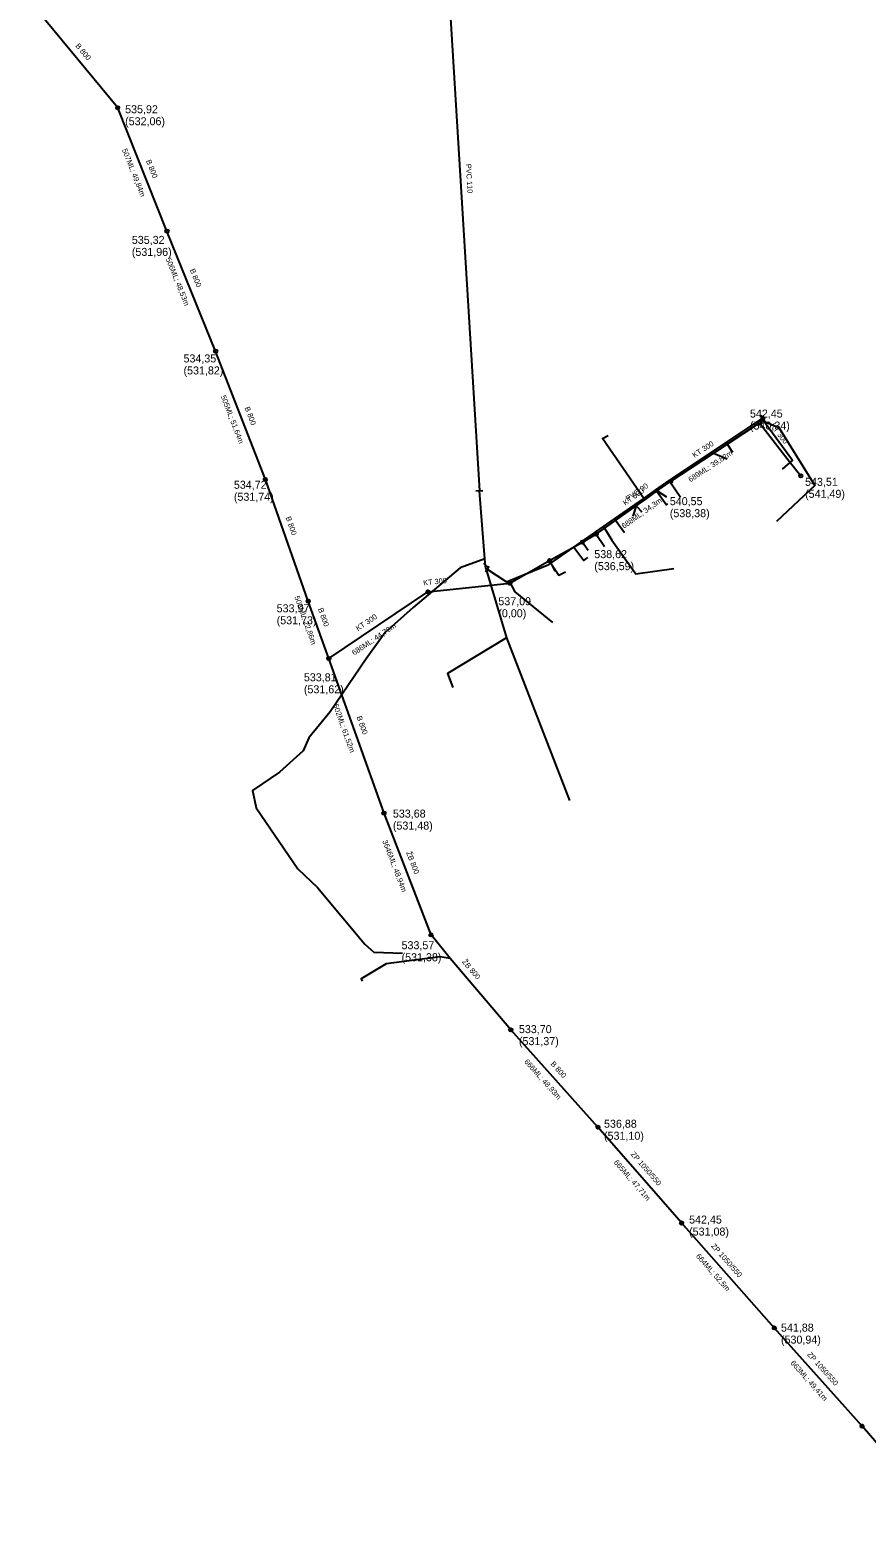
# Model space of a CAD drawing. Extents: x -867696 to -865033, y -1042522 to -1039817.
# Drawn here: x -867085 to -866771, y -1041066 to -1040505 of the extents above; entities that cross this region are included whole.
import ezdxf

# ---------------------------------------------------------------- set-up
doc = ezdxf.new("R2010")
doc.units = 0
for name, color, linetype in [('KN - jednotna', 7, 'Continuous'), ('KN - popis material', 7, 'Continuous'), ('KN - popis ostatni', 7, 'Continuous'), ('KN - popis usek delka', 7, 'Continuous'), ('KN - pripojka', 7, 'Continuous'), ('KN - sachta komora', 7, 'Continuous'), ('Level 1', 7, 'Continuous'), ('V - armatura', 7, 'Continuous'), ('V - hydrant', 7, 'Continuous'), ('V - ostatni', 7, 'Continuous'), ('V - popis material', 7, 'Continuous'), ('V - pripojka', 7, 'Continuous'), ('V - rozvadeci', 7, 'Continuous')]:
    doc.layers.add(name, color=color, linetype=linetype)

# ---------------------------------------------------------------- blocks, each defined once
blk = doc.blocks.new('100.M')
at = {"layer": 'Level 1'}
blk.add_circle((0, 0), 1.27, dxfattribs=at)
blk = doc.blocks.new('147')
at = {"layer": 'Level 1'}
blk.add_line((0, 1.27), (0, -1.27), dxfattribs=at)
blk = doc.blocks.new('111')
at = {"layer": 'Level 1'}
for p, q in [((0.42, 0.72), (-0.83, 0)), ((-0.83, 0), (0.42, -0.72)), ((0.42, -0.72), (0.42, 0.72))]:
    blk.add_line(p, q, dxfattribs=at)
blk = doc.blocks.new('150')
at = {"layer": 'Level 1'}
blk.add_line((0, 1.27), (0, -1.27), dxfattribs=at)

msp = doc.modelspace()

# ---------------------------------------------------------------- linework, layer by layer
at = {"layer": 'KN - jednotna'}
for points in [[(-867051.86, -1040533.696), (-867084.758, -1040493.849)], [(-867033.387, -1040579.988), (-867051.86, -1040533.696)], [(-867015.14, -1040624.958), (-867033.387, -1040579.988)], [(-866996.489, -1040673.109), (-867015.14, -1040624.958)], [(-866844.519, -1040673.759), (-866828.494, -1040663.228), (-866811.239, -1040651.889)], [(-866811.239, -1040651.889), (-866800.098, -1040666.197), (-866795.808, -1040671.708)], [(-866980.429, -1040718.699), (-866996.489, -1040673.109)], [(-866872.488, -1040693.608), (-866857.438, -1040682.927), (-866853.868, -1040680.394), (-866849.593, -1040677.36), (-866844.519, -1040673.759)], [(-866877.65, -1040696.53), (-866872.488, -1040693.608)], [(-866889.957, -1040703.496), (-866877.65, -1040696.53)], [(-866904.838, -1040711.918), (-866889.957, -1040703.496)], [(-866935.547, -1040715.219), (-866904.838, -1040711.918)], [(-866972.71, -1040740.217), (-866980.429, -1040718.699)], [(-866972.71, -1040740.217), (-866935.547, -1040715.219)], [(-866952.026, -1040798.158), (-866972.71, -1040740.217)], [(-866934.406, -1040843.818), (-866952.026, -1040798.158)], [(-866904.477, -1040879.417), (-866927.21, -1040852.65), (-866934.406, -1040843.818)], [(-866871.827, -1040915.857), (-866904.477, -1040879.417)], [(-866840.458, -1040951.798), (-866871.827, -1040915.857)], [(-866805.698, -1040991.149), (-866840.458, -1040951.798)], [(-866772.797, -1041028.018), (-866805.698, -1040991.149)], [(-866739.728, -1041066.158), (-866772.797, -1041028.018)]]:
    msp.add_lwpolyline(points, dxfattribs=at)
at = {"layer": 'KN - pripojka'}
for points in [[(-866828.494, -1040663.228), (-866823.385, -1040665.384)], [(-866849.593, -1040677.36), (-866846.17, -1040679.577)], [(-866857.438, -1040682.927), (-866858.683, -1040686.861)], [(-866857.438, -1040682.927), (-866855.321, -1040685.18)], [(-866872.488, -1040693.608), (-866869.328, -1040698.253)], [(-866877.65, -1040696.53), (-866875.491, -1040699.561)], [(-866889.957, -1040703.496), (-866888.004, -1040707.498)], [(-866927.21, -1040852.65), (-866931.02, -1040852), (-866951.25, -1040854.6), (-866960.63, -1040860.31), (-866960.153, -1040861.114)]]:
    msp.add_lwpolyline(points, dxfattribs=at)
at = {"layer": 'V - pripojka'}
for points in [[(-866810.732, -1040650.56), (-866810.59, -1040650.78), (-866804.06, -1040653.54), (-866790.498, -1040675.353), (-866804.935, -1040688.853)], [(-866810.273, -1040650.23), (-866810.11, -1040650.46), (-866798.86, -1040665.773), (-866802.735, -1040669.148)], [(-866810.085, -1040650.089), (-866809.931, -1040649.988)], [(-866854.623, -1040680.143), (-866870.15, -1040657.73), (-866868.025, -1040656.605)], [(-866823.727, -1040659.218), (-866821.412, -1040662.777)], [(-866845.083, -1040673.5), (-866840.918, -1040679.644)], [(-866850.111, -1040677), (-866846.083, -1040682.559), (-866845.674, -1040682.044)], [(-866869.723, -1040690.658), (-866866.647, -1040695.841), (-866857.643, -1040708.399), (-866843.392, -1040706.436)], [(-866865.575, -1040687.769), (-866861.856, -1040693.007)], [(-866880.902, -1040698.443), (-866877.088, -1040703.418), (-866875.665, -1040702.267)], [(-866914.22, -1040702.86), (-866923.46, -1040706.14), (-866941.08, -1040721.05), (-866951.56, -1040730.48), (-866958.71, -1040740.28), (-866972.21, -1040760.18), (-866980.17, -1040769.93), (-866982.28, -1040774.74), (-866991.15, -1040782.83), (-867001.38, -1040789.62), (-866999.9, -1040796.16), (-866984.31, -1040819.04), (-866977, -1040826.08), (-866959.24, -1040847.3), (-866955.82, -1040850.21), (-866945.12, -1040850.7)], [(-866913.969, -1040705.486), (-866913.613, -1040705.148)], [(-866913.884, -1040706.468), (-866906.046, -1040732.477), (-866882.455, -1040793.43)], [(-866889.536, -1040704.455), (-866886.503, -1040708.972), (-866883.964, -1040707.665)], [(-866905.184, -1040711.021), (-866905.09, -1040711.24), (-866902.965, -1040715.178), (-866888.84, -1040726.74)], [(-866906.046, -1040732.477), (-866928.207, -1040745.759), (-866926.188, -1040751.067)]]:
    msp.add_lwpolyline(points, dxfattribs=at)
at = {"layer": 'V - rozvadeci'}
for points in [[(-866924.552, -1040322.871), (-866924.327, -1040324.846), (-866937.332, -1040332.974), (-866916.288, -1040677.377)], [(-866913.309, -1040706.74), (-866906.152, -1040711.396), (-866905.184, -1040711.021), (-866890.229, -1040704.938), (-866889.536, -1040704.455), (-866880.902, -1040698.443), (-866869.723, -1040690.658), (-866865.575, -1040687.769), (-866854.623, -1040680.143), (-866850.111, -1040677), (-866845.083, -1040673.5), (-866823.727, -1040659.218), (-866810.732, -1040650.56), (-866810.503, -1040650.404), (-866810.273, -1040650.23), (-866810.085, -1040650.089)], [(-866913.884, -1040706.468), (-866913.969, -1040705.486), (-866914.22, -1040702.86), (-866916.288, -1040677.377)], [(-866913.884, -1040706.468), (-866913.309, -1040706.74)]]:
    msp.add_lwpolyline(points, dxfattribs=at)

# ---------------------------------------------------------------- block references
at = {"layer": 'KN - sachta komora'}
for p, xscale, yscale, rotation in [((-867051.86, -1040533.696), 0.5000000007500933, 0.5000000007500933, 120.99999982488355), ((-867033.387, -1040579.988), 0.5000000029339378, 0.5000000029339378, 111.99999900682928), ((-867015.14, -1040624.958), 0.5000000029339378, 0.5000000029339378, 111.99999900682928), ((-866811.239, -1040651.889), 0.5041888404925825, 0.5041888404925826, 168.37362119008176), ((-866996.489, -1040673.109), 0.5000000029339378, 0.5000000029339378, 111.99999900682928), ((-866844.519, -1040673.759), 0.5000000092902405, 0.5000000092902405, -144.99999976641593), ((-866795.808, -1040671.708), 0.5000000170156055, 0.5000000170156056, 128.00000040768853), ((-866877.65, -1040696.53), 0.4999999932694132, 0.4999999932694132, 30.00000044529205), ((-866872.488, -1040693.608), 0.4999999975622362, 0.4999999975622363, -146.99999872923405), ((-866889.957, -1040703.496), 0.4999999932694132, 0.4999999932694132, 30.00000044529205), ((-866904.838, -1040711.918), 0.516753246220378, 0.516753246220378, 23.041281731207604), ((-866980.429, -1040718.699), 0.4999999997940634, 0.4999999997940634, 110.00000065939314), ((-866935.547, -1040715.219), 0.5137536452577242, 0.513753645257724, 24.689105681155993), ((-866972.71, -1040740.217), 0.4999999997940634, 0.4999999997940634, -69.99999934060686), ((-866952.026, -1040798.158), 0.4999999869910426, 0.4999999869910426, -68.99999941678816), ((-866934.406, -1040843.818), 0.5000000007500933, 0.5000000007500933, -59.00000017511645), ((-866904.477, -1040879.417), 0.5000000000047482, 0.5000000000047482, -47.99999869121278), ((-866871.827, -1040915.857), 0.5000000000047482, 0.5000000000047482, 132.0000013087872), ((-866840.458, -1040951.798), 0.5000000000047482, 0.5000000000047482, 132.0000013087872), ((-866805.698, -1040991.149), 0.5000000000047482, 0.5000000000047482, 132.0000013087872), ((-866772.797, -1041028.018), 0.5000000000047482, 0.5000000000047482, 132.0000013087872)]:
    msp.add_blockref('100.M', p, dxfattribs=dict(at, xscale=xscale, yscale=yscale, rotation=rotation))
at = {"layer": 'V - armatura'}
for p, xscale, yscale, rotation in [((-866916.288, -1040677.377), 1.000000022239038, 1.0000000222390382, -85.00000001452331), ((-866913.309, -1040706.74), 1.0037042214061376, 1.0037042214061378, -29.379208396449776)]:
    msp.add_blockref('147', p, dxfattribs=dict(at, xscale=xscale, yscale=yscale, rotation=rotation))
at = {"layer": 'V - hydrant'}
for p, xscale, yscale, rotation in [((-866809.986, -1040650.024), 0.9999999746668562, 0.999999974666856, 34.00000045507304), ((-866913.792, -1040705.319), 1.0000000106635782, 1.0000000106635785, 44.00000165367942)]:
    msp.add_blockref('150', p, dxfattribs=dict(at, xscale=xscale, yscale=yscale, rotation=rotation))
at = {"layer": 'V - ostatni', "xscale": 0.9999999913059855, "yscale": 0.9999999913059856, "rotation": 37.00000193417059}
msp.add_blockref('111', (-866810.085, -1040650.089), dxfattribs=at)

# ---------------------------------------------------------------- texts
at = {"layer": 'KN - popis material'}
for s, height, rotation, p in [('B 800', 2, 309.54, (-867067.836, -1040510.575)), ('B 800', 2, 291.75, (-867041.317, -1040553.64)), ('B 800', 2, 292.09, (-867024.905, -1040594.51)), ('B 800', 2, 291.17, (-867004.335, -1040646.206)), ('KT 300', 2, 307.9, (-866807.386, -1040652.931)), ('KT 300', 2, 33.31, (-866835.616, -1040665.036)), ('KT 300', 2, 35.36, (-866861.585, -1040682.928)), ('B 800', 2, 289.41, (-866988.929, -1040687.347)), ('KT 300', 2, 6.14, (-866937.226, -1040712.84)), ('B 800', 2, 289.73, (-866976.833, -1040721.617)), ('KT 300', 2, 33.93, (-866961.772, -1040729.967)), ('B 800', 2, 289.65, (-866962.348, -1040762.107)), ('ŽB 800', 2, 291.1, (-866943.766, -1040812.897)), ('ŽB 800', 2, 310.34, (-866922.939, -1040853.961)), ('B 800', 2, 311.86, (-866889.731, -1040892.279)), ('ZP 1050/550', 1.99999, 311.11, (-866859.706, -1040926.094)), ('ZP 1050/550', 1.99999, 311.46, (-866829.54, -1040960.534)), ('ZP 1050/550', 1.99999, 311.74, (-866793.503, -1041001.208))]:
    msp.add_text(s, height=height, rotation=rotation, dxfattribs=at).set_placement(p)
at = {"layer": 'KN - popis ostatni'}
for s, p in [('535,92 ', (-867049.08, -1040535.776)), ('(532,06)', (-867049.08, -1040540.276)), ('535,32 ', (-867046.567, -1040584.758)), ('(531,96)', (-867046.567, -1040589.258)), ('534,35 ', (-867027.19, -1040629.188)), ('(531,82)', (-867027.19, -1040633.688)), ('542,45 ', (-866814.829, -1040649.859)), ('(540,34)', (-866814.829, -1040654.359)), ('534,72 ', (-867008.309, -1040676.549)), ('543,51 ', (-866794.168, -1040675.448)), ('(531,74)', (-867008.309, -1040681.049)), ('(541,49)', (-866794.168, -1040679.948)), ('540,55 ', (-866844.879, -1040682.699)), ('(538,38)', (-866844.879, -1040687.199)), ('538,62 ', (-866873.188, -1040702.558)), ('(536,59)', (-866873.188, -1040707.058)), ('537,09 ', (-866909.168, -1040720.218)), ('533,97 ', (-866992.269, -1040722.859)), ('(531,73)', (-866992.269, -1040727.359)), ('(0,00)', (-866909.168, -1040724.718)), ('533,81 ', (-866982.06, -1040748.727)), ('(531,62)', (-866982.06, -1040753.227)), ('533,68 ', (-866948.696, -1040799.818)), ('(531,48)', (-866948.696, -1040804.318)), ('533,57 ', (-866945.446, -1040849.168)), ('(531,38)', (-866945.446, -1040853.668)), ('533,70 ', (-866901.447, -1040880.627)), ('(531,37)', (-866901.447, -1040885.127)), ('536,88 ', (-866869.537, -1040916.097)), ('(531,10)', (-866869.537, -1040920.597)), ('542,45 ', (-866837.648, -1040952.018)), ('(531,08)', (-866837.648, -1040956.518)), ('541,88 ', (-866803.198, -1040992.519)), ('(530,94)', (-866803.198, -1040997.019))]:
    msp.add_text(s, height=3, dxfattribs=at).set_placement(p)
at = {"layer": 'KN - popis usek delka'}
for s, rotation, p in [('507ML; 49,84m', 291.75, (-867050.301, -1040549.472)), ('506ML; 48,53m', 292.09, (-867033.914, -1040590.395)), ('505ML; 51,64m', 291.17, (-867013.276, -1040641.948)), ('689ML; 39,82m', 33.31, (-866837.146, -1040674.178)), ('688ML; 34,3m', 35.36, (-866862.054, -1040691.598)), ('503ML; 22,86m', 289.73, (-866985.664, -1040717.135)), ('686ML; 44,79m', 33.93, (-866963.204, -1040739.126)), ('502ML; 61,52m', 289.65, (-866971.174, -1040757.611)), ('3646ML; 48,94m', 291.1, (-866952.701, -1040808.628)), ('666ML; 48,93m', 311.86, (-866899.6, -1040891.454)), ('665ML; 47,71m', 311.11, (-866866.013, -1040929.209)), ('664ML; 52,5m', 311.46, (-866835.232, -1040964.361)), ('663ML; 49,41m', 311.74, (-866799.776, -1041004.393))]:
    msp.add_text(s, height=1.99999, rotation=rotation, dxfattribs=at).set_placement(p)
at = {"layer": 'V - popis material'}
for s, rotation, p in [('PVC 110', 273.5, (-866921.373, -1040554.811)), ('PVC 90', 34.85, (-866860.559, -1040681.351))]:
    msp.add_text(s, height=2, rotation=rotation, dxfattribs=at).set_placement(p)

doc.saveas('drawing.dxf')
